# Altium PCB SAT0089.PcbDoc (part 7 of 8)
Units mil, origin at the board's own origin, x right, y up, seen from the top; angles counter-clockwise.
Board outline 4075 x 2715 mil, 6 copper layers (Top Layer, InternalPlane1, MidLayer1, Internal Plane 3, InternalPlane2, Bottom Layer), stack 67.4 mil thick; 538 components, 405 nets, 1716 pads, 1236 vias.
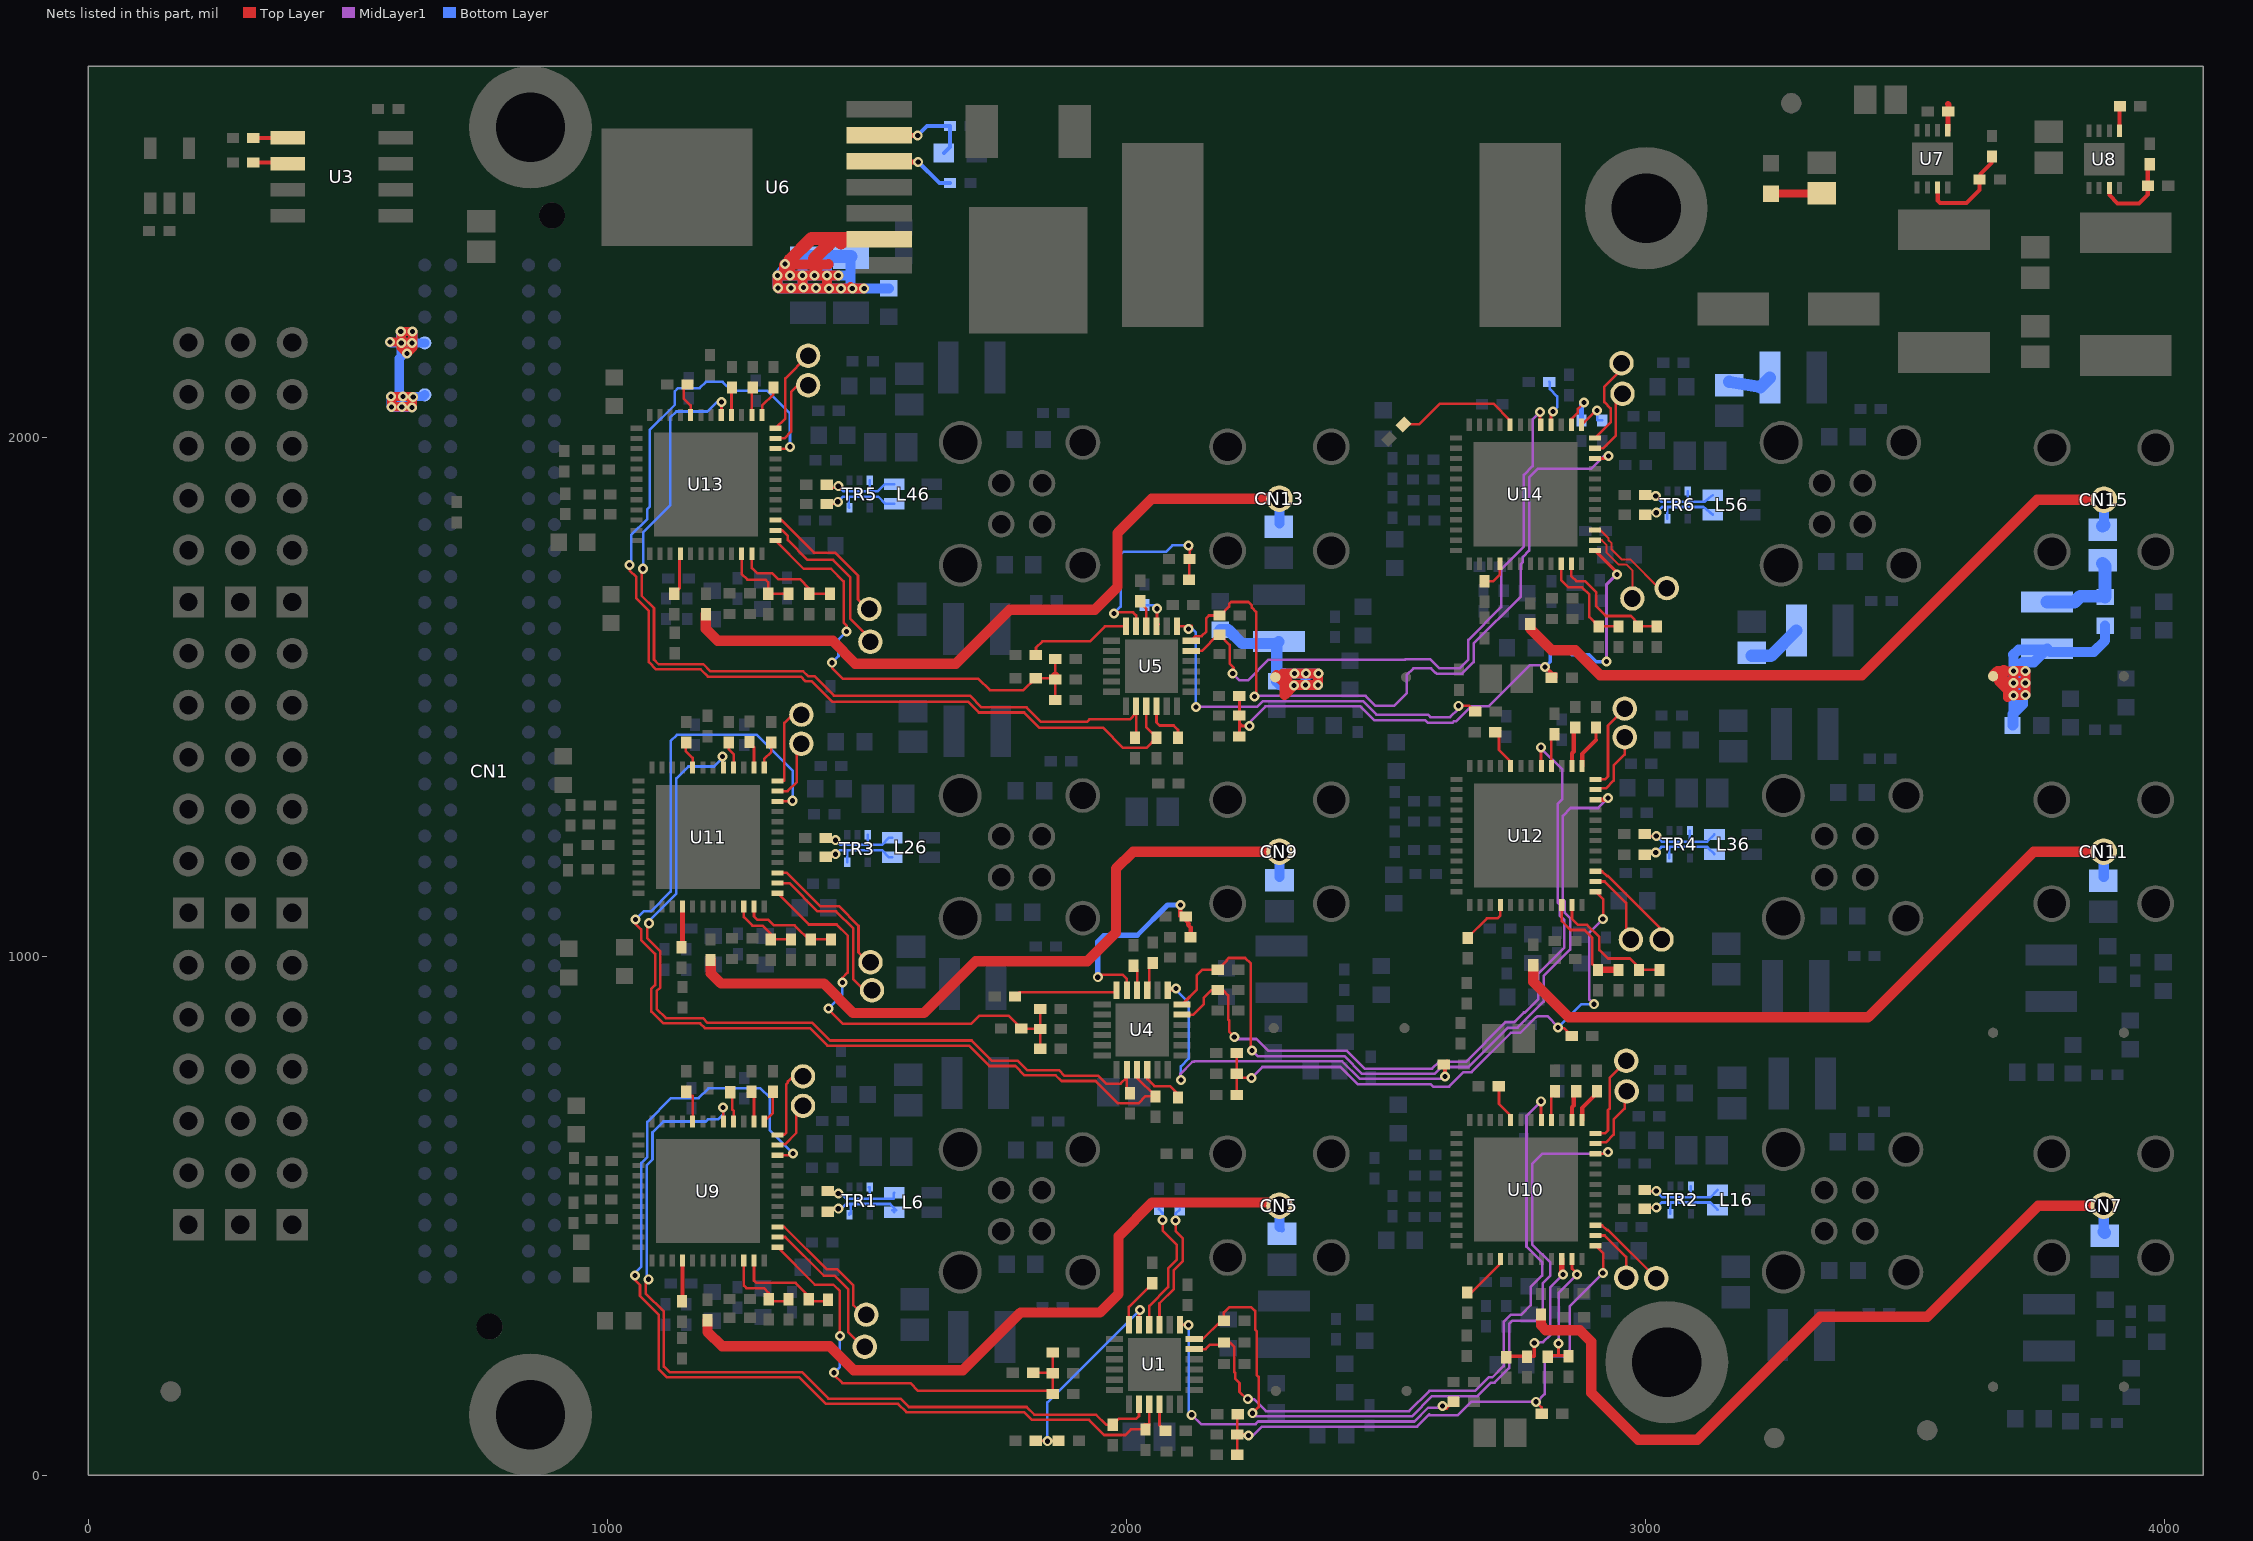
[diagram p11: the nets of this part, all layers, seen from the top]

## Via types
v1: diameter 19.29, hole 9.84, Top Layer to Bottom Layer, tented both sides, 1155 vias
v2: diameter 19.68, hole 7.87, Top Layer to Bottom Layer, tented both sides, 80 vias
v3: diameter 22, hole 10, Top Layer to Bottom Layer, tented both sides, 1 vias

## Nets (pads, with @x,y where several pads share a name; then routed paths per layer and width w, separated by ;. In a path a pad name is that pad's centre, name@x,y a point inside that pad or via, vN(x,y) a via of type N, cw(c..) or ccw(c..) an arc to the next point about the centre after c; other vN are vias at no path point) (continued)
NetL48_2: L48.2 L49.1 R125.2 R126.1 | length 719.7
  Top Layer w8: v1(2323,1522) 2315.72,1522 2314.72,1523 2292.36,1545.35 2323.65,1545.35 v1(2324,1545)
  Top Layer w19.29: L49.1@2288.98,1541.94 2305,1525.92 ; 2301.85,1545 v1(2324,1545) v1(2346,1545) v1(2370,1545) 2369,1544 v1(2369,1523) v1(2345,1523) v1@2323,1523 ; 2305,1525.92 2307.92,1523 2314.72,1523 2316.68,1523 v1@2323,1523 ; 2305,1525.92 2305,1504 v1(2323,1522) v1@2323,1523
  Top Layer w19.68: 2301.85,1545 2298.27,1541.42 v1@2316.68,1523
  Bottom Layer w19.29: R126.1@2297.5,1523 v1@2323,1523 ; R126.1@2304.5,1545 v1(2324,1545) v1(2346,1545) ; v1(2323,1522) v1@2323,1523 ; v1(2369,1523) v1(2345,1523) ; v1(2370,1545) v1(2346,1545) ; v1@2323,1523 v1(2345,1523) ; v1(2345,1523) 2345,1544 v1(2346,1545)
  Bottom Layer w22: R125.2@2181,1629.5 2196.5,1629.5 2223,1603 L48.2@2290.28,1603 ; L48.2@2294,1606.72 L48.2@2290.28,1603 ; R126.1@2297.5,1523 R126.1@2290,1530.5 ; R126.1@2304.5,1545 R126.1@2290,1530.5 ; R126.1@2290,1530.5 R126.1@2290,1530.56 2290,1602.72 L48.2@2290.28,1603
NetL54_1: L54.1 R146.1 | length 86.2
  Bottom Layer w24: R146.1@3162,2107 3163.06,2106.82 3221.56,2097 L54.1@3239.84,2115.28
NetL55_1: L55.1 R147.1 | length 106
  Bottom Layer w24: R147.1@3205,1579 3241.72,1579 L55.1@3290.72,1628
NetL58_1: L58.1 R148.1 R149.1 | length 183.6
  Bottom Layer w25: L58.1@3774,1683.28 3827.28,1683.28 3838,1694 3884.5,1694 3886,1692.5 R149.1@3886,1692.56 3886,1752 R148.1@3881,1757
NetL58_2: L58.2 L59.1 R149.2 R150.1 | length 932.7
  Top Layer w17.72: v1(3709,1503) 3702,1503 3698,1499 3698,1514 3698,1520.92 3680.89,1538.03 3674.98,1543.94 3681.05,1550 3690.89,1550 v1(3709,1550)
  Top Layer w19.29: L59.1@3671.98,1543.94 3678.05,1550 3681.05,1550 ; 3680.89,1540 3680.89,1538.03 3680.89,1531.11 3698,1514 v1(3709,1503) ; 3693.89,1527 v1(3709,1527) ; v1(3709,1503) v1(3709,1527) ; v1(3709,1503) 3710,1504 v1(3732,1504) v1(3732,1527) ; v1(3709,1527) v1(3709,1550) v1(3732,1550) v1(3732,1527) ; v1(3709,1527) v1(3732,1527)
  Top Layer w24: 3690.89,1550 3680.89,1540 3693.89,1527
  Bottom Layer w19.29: R150.1@3709,1446.5 3709,1468 v1(3709,1503) v1(3709,1527) v1(3709,1550) 3709,1581 ; v1@3727,1504 v1(3732,1504) ; v1@3727,1527 v1(3732,1527) ; v1@3727,1550 v1(3732,1550) ; L58.2@3774,1592.72 3779.72,1587 3864,1587 3886,1609 R149.2@3886,1637.44 R149.2@3886,1637.5
  Bottom Layer w20: R150.1@3709,1446.5 3707.5,1445 3707.5,1466.5 3709,1468 3727,1486 3727,1504 3727,1527 3727,1550 3727,1567 3748.28,1567 L58.2@3772.28,1591 ; 3709,1581 3719,1591 L58.2@3772.28,1591 ; L58.2@3774,1592.72 L58.2@3772.28,1591
NetLD1_2: LD1.2 R16.1 | length 93
  Top Layer w16: LD1.2@3247,2470.04 R16.1@3340,2470.47
NetR2_1: R2.1 R3.1 U1.11 | length 399.4
  Top Layer w5: R2.1@1826,67 1847,67 v1(1848,66) 1849,67 R3.1@1869,67 ; U1.11@2024.47,290.77 2024.47,317.47 v1(2026,319)
  Bottom Layer w5: v1(1848,66) 1848,141 v1(2026,319)
NetR4_1: R4.1 U1.12 | length 98
  Top Layer w5: U1.12@2004.79,290.77 2004.79,324.79 R4.1@2050,370
NetR5_2: R5.2 U3.1 | length 67
  Top Layer w8: R5.2@318.27,2576.85 318.46,2577.05 U3.1@385.21,2577.05
NetR6_1: R6.1 U3.2 | length 68
  Top Layer w8: R6.1@318.27,2529.61 382.65,2529.61 U3.2@385.21,2527.05
NetR7_1: R7.1 R8.1 U4.11 | length 419.6
  Top Layer w5: v1@1945.5,959.5 v1(1945,960) 1950,965 1993,965 2001.02,956.98 U4.11@2001.02,935.12
  Top Layer w8: v1(2104,1099) 2104,1078 2106,1076 2107,1077 R8.1@2114.68,1077 2115,1077 2115,1069 2121,1063 2119,1061 2124,1056 R7.1@2124,1037
  Bottom Layer w10: v1(1945,960) 1945,1029 1956,1040 1967,1040 1968,1041 2021,1041 2079,1099 v1(2104,1099)
NetR9_1: R9.1 U4.12 | length 200.4
  Top Layer w5: R9.1@1786,923 1794,931 1977.22,931 U4.12@1981.34,935.12
NetR10_1: R10.1 R11.1 U5.11 | length 396.4
  Top Layer w5: v1(1976,1661) 1978,1663 2013,1663 2018.74,1657.26 U5.11@2018.74,1635.91 ; v1(2120,1792) 2119,1791 2125,1785 2122,1782 2122,1765 2124,1763 2121,1760 R10.1@2121,1726
  Bottom Layer w5: v1(1976,1661) 1989,1674 1989,1774 1995,1780 2077,1780 2089,1792 v1(2120,1792)
NetR12_1: R12.1 U5.12 | length 204
  Top Layer w5: R12.1@1826,1581 1826,1595 1838,1607 1930,1607 1958.91,1635.91 U5.12@1999.06,1635.91
NetR13_2: R13.2 R14.1 U6.6 | length 183.1
  Top Layer w9.84: U6.6@1542,2583 1543,2582 v1(1598,2582)
  Bottom Layer w8: v1(1598,2582) 1616,2600 R13.2@1660.31,2600 1660.31,2559.81 R14.1@1648.5,2548
NetR15_1: R15.1 U6.5 | length 136.1
  Top Layer w9.84: U6.5@1542,2533 1544,2531 v1(1599,2531)
  Bottom Layer w8: v1(1599,2531) 1640,2490 R15.1@1660.32,2490
NetR17_1: R17.1 U7.5 | length 65.8
  Top Layer w9.84: U7.5@3582.98,2591.66 3582.98,2642.53
  Top Layer w11.81: 3582.98,2642.53 3584,2641.51 R17.1@3584,2628
NetR18_1: R18.1 U8.5 | length 50.4
  Top Layer w7.87: U8.5@3913.69,2587.72 3913.69,2637.69 R18.1@3914,2638
NetR19_1: R19.1 R20.1 U7.3 | length 198
  Top Layer w8: U7.3@3563.3,2481.43 3563.3,2456.7 3568,2452 3619,2452 3643.69,2476.69 3643.69,2497.17 3645.69,2499.17 3645.69,2507.69 3667,2529 R20.1@3667,2538.81 ; R20.1@3667,2538.81 3667,2540 3668,2541 3664.81,2541 R20.1@3667,2538.81
NetR21_1: R21.1 R22.1 U8.3 | length 157.8
  Top Layer w7.87: U8.3@3894.01,2477.49 3894.01,2466.99 3910,2451 3951,2451 3968,2468 3968,2522 R22.1@3972,2526
NetR32_2: R32.2 U9.8 | length 69.6
  Top Layer w5: R32.2@1152,739 1152,731.53 1164.47,731.53 U9.8@1164.47,681.86
NetR33_2: R33.2 U9.28 | length 78.5
  Top Layer w7.01: R33.2@1144,336 1144.79,336.79 U9.28@1144.79,414.14
NetR34_2: R34.2 R38.1 U9.35 | length 202.2
  Top Layer w5: U9.35@1282.58,414.14 1282.58,375.42 1287,371 1363,371 1388,346 1388,340 1392,336 1422,336 R38.1@1425,339
NetR35_2: R35.2 R39.1 U9.34 | length 155.3
  Top Layer w5: U9.34@1262.9,414.14 1262.9,366.1 1268,361 1302,361 1311,352 1311,340 1315,336 1345,336 R35.2@1349,340
NetR36_1: R36.1 U9.1 | length 64.1
  Top Layer w5: U9.1@1302.27,681.86 1319,698.59 R36.1@1319,739
NetR37_2: R37.2 U9.2 | length 59
  Top Layer w5: R37.2@1278,739 1282.58,734.42 U9.2@1282.58,681.86
NetR42_1: R42.1 U9.4 | length 58.7
  Top Layer w5: R42.1@1237,738 1241,734 1241,705 1243.21,702.79 U9.4@1243.21,681.86
NetR44_2: R44.2 R45.2 R48.2 R49.2 U9.37 | length 874.6
  Top Layer w5: U9.37@1327.86,439.81 1400.17,367.5 1435.5,367.5 1448,355 v1(1448,269) ; v1(1437,198) 1437,194 1453,178 1584,178 1599,163 1852,163 1858,157 R48.2@1858,197 ; R44.2@1821,198 1857,198 R48.2@1858,197 ; R45.2@1858,237 R48.2@1858,197
  Bottom Layer w5: v1(1437,198) 1448,209 v1(1448,269)
NetR58_2: R58.2 U10.8 | length 74.5
  Top Layer w5: R58.2@2718,750 2718,716 2740.47,693.53 U10.8@2740.47,684.86
NetR59_2: R59.2 R63.1 U10.35 | length 247.5
  Top Layer w5: U10.35@2858.58,417.14 2858.58,398.42 2868,389 v1(2868,387)
  Top Layer w6: R59.2@2812,229 2812,231 2833,231 ; v1(2833,254) 2833,231 ; R63.1@2852,230 2852,231 2833,231
  MidLayer1 w5: v1(2833,254) 2833,352 v1(2868,387)
NetR60_2: R60.2 R64.1 U10.34 | length 279.5
  Top Layer w6: R64.1@2732,228 2732,229.77 R60.2@2772,229.77 ; R60.2@2772,229 R60.2@2772,229.77 ; v1(2786,255) 2786,229.77 R60.2@2772,229.77
  Top Layer w9.84: v1@2838.9,389.1 U10.34@2838.9,417.14
  Top Layer w12: v1@2838.9,389.1 v1(2841,387)
  MidLayer1 w5: v1@2784,257 v1@2786,257 ; v1(2786,255) v1@2786,257 ; v1(2841,387) 2817,363 2817,271 2803,257 v1@2786,257
NetR61_1: R61.1 U10.1 | length 67.6
  Top Layer w8: U10.1@2878.27,684.86 2878.27,708.27 2906,736 2907,736 R61.1@2907,740
NetR62_2: R62.2 U10.2 | length 61.6
  Top Layer w8: U10.2@2858.58,684.86 2858.58,709.58 2862,713 2862,734 2867,734 R62.2@2867,740
NetR66_1: R66.1 U10.4 | length 62.4
  Top Layer w5: U10.4@2819.21,684.86 2819,684.86 2819,733 2826,733 R66.1@2826,740
NetR68_2: R68.2 R71.2 R72.2 R73.2 U10.37 | length 1091.3
  Top Layer w5: R71.2@2214,40 R72.2@2214,79 ; R73.2@2215,118 2215,117 2214,117 R72.2@2214,79 ; v1(2235,77) 2233,79 R72.2@2214,79 ; R68.2@2800,119 2800,131 v1(2789,142) ; U10.37@2903.86,442.81 2919,427.67 2919,395 2918,395 v1(2918,390) ; v1(2789,142) 2789,143 2790,143 v1(2789,142)
  MidLayer1 w5: v1(2235,77) 2244,77 2261,94 2560,94 2583.5,117.5 2585,116 2638.5,116 2664.5,142 v1(2789,142) 2791,142 2806,157 2806,219 2817,230 2842,230 2854,242 2854,326 v1(2918,390)
NetR82_2: R82.2 U11.8 | length 54.1
  Top Layer w5: R82.2@1152,1412 1151,1411 1151,1396 1164.47,1382.53 U11.8@1164.47,1363.86
NetR83_2: R83.2 R87.1 U11.35 | length 191.4
  Top Layer w5: U11.35@1282.58,1096.14 1282.58,1077 1288.58,1071 1310,1071 1321,1060 1361,1060 1392,1029 R83.2@1392,1032.69 1392,1033 R87.1@1431,1033
NetR84_2: R84.2 R88.1 U11.34 | length 135.1
  Top Layer w5: U11.34@1262.9,1096.14 1262.9,1076.1 1279.5,1059.5 1299,1059.5 1315,1043.5 1315,1033 R84.2@1354,1033
NetR85_1: R85.1 U11.1 | length 53.8
  Top Layer w5: U11.1@1302.27,1363.86 1302.27,1380.27 1316,1394 R85.1@1316,1412
NetR86_2: R86.2 U11.2 | length 51.7
  Top Layer w5: R86.2@1274,1412 1282.58,1403.42 U11.2@1282.58,1363.86
NetR90_1: R90.1 U11.4 | length 52
  Top Layer w5: R90.1@1234,1412 1234,1399 1243.21,1389.79 U11.4@1243.21,1363.86
NetR92_2: R92.2 R95.2 R96.2 R97.2 U11.37 | length 847.1
  Top Layer w5: U11.37@1327.86,1121.81 1388.17,1061.5 1442,1061.5 1463.25,1040.25 1463,1040 1463,969 1453,959 v1(1453,950) ; v1(1426,900) 1426,898 1454,870 1701,870 1717,886 1773,886 1798,861 1833,861 R96.2@1834,860 ; R97.2@1834,822 R96.2@1834,860 ; R95.2@1834,899 R96.2@1834,860
  Bottom Layer w5: v1(1426,900) v1@1428,900 ; v1@1431,897 v1@1428,900 ; v1(1453,950) 1453,927 1427,901 v1@1428,900
NetR106_2: R106.2 U12.8 | length 85.7
  Top Layer w5: R106.2@2711,1432 2713,1434 2717,1434 2718,1435 2718,1398 2740.47,1375.53 U12.8@2740.47,1366.86
NetR107_2: R107.2 R111.1 U12.35 | length 252.8
  Top Layer w5: U12.35@2858.58,1099.14 2858.58,1072.42 2870,1061 2888,1061 2911.5,1037.5 2911.5,1012.5 2928,996 2970,996 2987.65,978.35 2987.65,974.37 R111.1@3027.02,974.37
NetR108_2: R108.2 R112.1 U12.34 | length 209
  Top Layer w5: U12.34@2838.9,1099.14 2838.9,1068.1 2856,1051 2883,1051 2898,1036 2898,985.28 R112.1@2908.91,974.37
  Top Layer w12: R112.1@2908.91,974.37 R108.2@2948.28,974.37
NetR109_1: R109.1 U12.1 | length 85.2
  Top Layer w6: 2905,1417 R109.1@2905,1441
  Top Layer w8: U12.1@2878.27,1366.86 2878.27,1390.27 2905,1417
NetR110_2: R110.2 U12.2 | length 76.8
  Top Layer w8: U12.2@2858.58,1366.86 2858.58,1391.58 2862,1395 2862,1438 R110.2@2865,1441
NetR114_1: R114.1 U12.4 | length 63.8
  Top Layer w5: U12.4@2819.21,1366.86 2819,1366.86 2819,1422 R114.1@2825,1428
NetR116_2: R116.2 R119.2 R120.2 R121.2 U12.37 | length 1158
  Top Layer w5: R119.2@2213,733 R120.2@2213,774 ; R121.2@2213,814 R120.2@2213,774 ; v1(2241,766) 2221,766 R120.2@2213,774 ; v1(2832,863) 2833,862 2843,862 R116.2@2858,847 ; U12.37@2903.86,1124.81 2919,1109.67 2919,1077 2918,1077 v1(2918,1072)
  MidLayer1 w5: v1@2240,769 2240,765 v1(2241,766) 2262,787 2412.5,787 2445.5,754 2586,754 2591,749 2622,749 2650,777 2665,777 2741,853 2759,853 2789,883 2790,883 2792,885 2811,885 2832,864 v1(2832,863) ; v1(2901,908) 2892,917 2892,1046 v1(2918,1072)
  Bottom Layer w5: v1(2832,863) 2877,908 v1(2901,908)
NetR130_2: R130.2 U13.8 | length 83.5
  Top Layer w5: U13.8@1160.47,2043.39 1160.47,2062 1147,2075.47 R130.2@1147,2094 ; R130.2@1147,2094 1147,2102 R130.2@1154.69,2102 1155,2102 R130.2@1147,2094
NetR131_2: R131.2 R135.1 U13.35 | length 204
  Top Layer w5: U13.35@1278.58,1775.67 1278.58,1748.42 1289,1738 1318,1738 1329,1727 1371,1727 1389,1709 1389,1699 R135.1@1429,1699
NetR132_2: R132.2 R136.1 U13.34 | length 157.3
  Top Layer w5: U13.34@1258.9,1775.67 1258.9,1737.1 1270,1726 1305,1726 1310,1721 1310,1699 R132.2@1349,1699
NetR133_1: R133.1 U13.1 | length 61.6
  Top Layer w5: U13.1@1298.27,2043.39 1298.27,2061.27 1320,2083 R133.1@1320,2096
NetR134_2: R134.2 U13.2 | length 53.2
  Top Layer w5: U13.2@1278.58,2043.39 1278.58,2094.58 R134.2@1280,2096
NetR138_1: R138.1 U13.4 | length 52.9
  Top Layer w5: U13.4@1239.21,2043.39 1239.21,2095.21 R138.1@1240,2096
NetR140_2: R140.2 R143.2 R144.2 R145.2 U13.37 | length 899.9
  Top Layer w5: U13.37@1323.86,1801.26 1378.2,1747 1431,1747 1455.5,1722.5 1455.5,1643 1461,1637.5 v1(1461,1626) ; v1(1433,1566) 1433,1556 1454,1535 1715,1535 1737,1513 1801.66,1513 1824.66,1536 R140.2@1825.69,1536 1860.46,1536 1862.91,1536 R144.2@1868,1536 ; R145.2@1862.91,1494.17 R144.2@1862.91,1533.54 ; R143.2@1862.91,1572.91 1862.91,1541.09 R144.2@1868,1536 ; R144.2@1870.46,1533.54 R144.2@1868,1536
  Top Layer w15.75: R144.2@1860.46,1536 1862.91,1533.54 1862.91,1536 R144.2@1862.91,1541.09
  Bottom Layer w5: v1(1433,1566) 1445.5,1578.5 1445.5,1610.5 v1(1461,1626)
NetR154_2: R154.2 U14.8 | length 244
  Top Layer w5: R154.2@2534.14,2025.14 2564.14,2025.14 2604,2065 2707,2065 2739.47,2032.53 U14.8@2739.47,2023.86
NetR155_2: R155.2 R159.1 U14.35 | length 247.9
  Top Layer w5: U14.35@2857.58,1756.67 2857.58,1732.42 2867,1723 2884,1723 2905,1702 2905,1675 2924,1656 2972,1656 2986,1642 2986,1636 R159.1@3022,1636
NetR156_2: R156.2 R160.1 U14.34 | length 203.8
  Top Layer w5: U14.34@2837.9,1756.67 2837.9,1725.1 2852,1711 2878,1711 2892,1697 2892,1654 2910,1636 R156.2@2948,1636
NetR157_1: R157.1 U14.1 | length 70.2
  Top Layer w5: U14.1@2877.27,2024.39 2904.88,2052 v1(2907,2052)
  Bottom Layer w5: v1(2907,2052) 2907,2033 R157.1@2917,2033
NetR158_2: R158.2 U14.2 | length 88.8
  Top Layer w5: U14.2@2857.58,2024.39 2857.58,2035.58 2870,2048 2870,2055 v1(2882,2067)
  Bottom Layer w10: R158.2@2877,2033 2877,2062 v1(2882,2067)
NetR162_1: R162.1 U14.4 | length 96.5
  Top Layer w5: U14.4@2818.21,2024.39 2818.21,2046.21 v1(2822,2050) v1@2824,2048
  Bottom Layer w5: R162.1@2815,2107 2816,2106 2816,2093 2830,2079 2830,2058 v1(2822,2050)
NetR164_2: R164.2 R167.2 R168.2 R169.2 U14.37 | length 1189.5
  Top Layer w5: R167.2@2218,1424 2218,1443 ; R169.2@2218,1502 2218,1450 ; v1(2237,1444) 2224,1444 ; 2218,1443 2218,1450 ; 2218,1443 2219,1444 2224,1444 ; 2218,1450 2224,1444
  Top Layer w6.5: U14.37@2902.86,1782.26 2945,1740.2 v1(2945,1736)
  Top Layer w8: v1(2807,1558) 2821,1544 2827,1544 2827,1537 R164.2@2819.31,1537 R164.2@2819,1537
  MidLayer1 w5: v1(2237,1444) 2237,1451 2268,1482 2451,1482 2478,1455 2576,1455 2580.5,1450.5 2628.5,1450.5 2631,1453 2635,1453 2664,1482 2698,1482 2777,1561 2804,1561 v1(2807,1558)
  MidLayer1 w6.5: v1(2925,1568) 2925,1716 v1(2945,1736)
  Bottom Layer w6.5: v1(2807,1558) v1@2809,1560 ; v1@2809,1562 v1@2809,1560 ; v1(2925,1568) 2905,1568 2892,1581 2858,1581 2847,1592 2826,1592 2817,1583 2817,1568 v1@2809,1560
NetR171_2: R171.2 U10.28 | length 99.5
  Top Layer w5: R171.2@2657,353 R171.2@2657,352.69 2657,350 2662,350 2720.79,408.79 U10.28@2720.79,417.14
NetR174_2: R174.2 U11.28 | length 78.9
  Top Layer w9.84: R174.2@1144.79,1020.14 U11.28@1144.79,1096.14
  Top Layer w10: R174.2@1142.76,1018.11 R174.2@1144.79,1020.14
NetR177_2: R177.2 U12.28 | length 101.5
  Top Layer w5: R177.2@2658,1036 2658,1037 2694.5,1073.5 2715.5,1073.5 2720.79,1078.79 U12.28@2720.79,1099.14
NetR180_2: R180.2 U13.28 | length 81.3
  Top Layer w5: R180.2@1128.98,1699.21 1139,1709.24 1139,1773.88 U13.28@1140.79,1775.67
NetR183_2: R183.2 U14.28 | length 56
  Top Layer w5: R183.2@2690,1723 2707,1723 2719.79,1735.79 U14.28@2719.79,1756.67
NetR185_1: R185.1 U1.9 | length 249.5
  Top Layer w5: U1.9@2063.84,290.77 2063.84,331.84 2091.5,359.5 2091.5,395.5 2109,413 2109,457 2095,471 v1(2095,491)
  Bottom Layer w5: v1(2095,491) 2095,504.5 R185.1@2103,512.5
NetR186_1: R186.1 U1.10 | length 258.6
  Top Layer w5: U1.10@2044.16,290.77 2044.16,326.66 2080.5,363 2080.5,399 2097.5,416 2097.5,444.5 2070,472 v1(2070,492)
  Bottom Layer w5: R186.1@2063,513 2070,506 v1(2070,492)
NetR187_1: R187.1 U4.10 | length 48.7
  Top Layer w5: R187.1@2014,981 2020.71,974.29 U4.10@2020.71,935.12
NetR188_1: R188.1 U4.9 | length 56.3
  Top Layer w5: U4.9@2040.39,935.12 2044,938.72 2044,980 R188.1@2051,987
NetR189_1: R189.1 U5.9 | length 64.4
  Top Layer w5: U5.9@2058.11,1635.91 2062,1639.8 2059,1642.8 v1(2059,1670)
  Bottom Layer w5: R189.1@2035,1677 2053,1677 2059,1671 v1(2059,1670)
NetR190_1: R190.1 U5.10 | length 52.8
  Top Layer w5: R190.1@2027,1684 2027,1681 2038,1670 2038,1661 2038.43,1660.57 U5.10@2038.43,1635.91
NetTP1_1: TP1.1 U9.38 | length 307.2
  Top Layer w5: U9.38@1327.86,459.42 1342.58,459.42 1417,385 1438,385 1464,359 1464,276 1494,246 1496,246 TP1.1@1496,248
NetTP2_1: TP2.1 U9.39 | length 266.3
  Top Layer w5: U9.39@1327.86,479.1 1340.9,479.1 1422.5,397.5 1442.5,397.5 1474,366 1474,328 1494,308 1499,308 TP2.1@1499,310
NetTP3_1: TP3.1 U9.48 | length 170.2
  Top Layer w5: U9.48@1327.86,656.27 1340,656.27 1345,661.27 1345,754 1348,757 1348,759 1373,784 1377,780 TP3.1@1377,769
NetTP4_1: TP4.1 U9.47 | length 115.1
  Top Layer w5: U9.47@1327.86,636.58 1329.28,638 1342,638 1364,660 1364,715 1367,712 TP4.1@1377,712
NetTP5_1: TP5.1 U10.38 | length 116.3
  Top Layer w5: U10.38@2903.86,462.42 2921.58,462.42 2963,421 TP5.1@2963,381
NetTP6_1: TP6.1 U10.39 | length 159.4
  Top Layer w5: U10.39@2903.86,482.1 2916.9,482.1 2926,473 2928,473 TP6.1@3021,380
NetTP7_1: TP7.1 U10.48 | length 175
  Top Layer w5: U10.48@2903.86,659.27 2922.27,659.27 2928,665 2928,704 2931,707 2931,766 2963,798 TP7.1@2963,799
NetTP8_1: TP8.1 U10.47 | length 135.7
  Top Layer w5: U10.47@2903.86,639.58 2906.28,642 2924,642 2939,657 2939,686 2960,707 2960,736 TP8.1@2964,740
NetTP9_1: TP9.1 U11.38 | length 325
  Top Layer w5: U11.38@1327.86,1141.42 1350.58,1141.42 1405,1087 1441,1087 1474,1054 1474,956 1495,935 TP9.1@1510,935
NetTP10_1: TP10.1 U11.39 | length 280.3
  Top Layer w5: U11.39@1327.86,1161.1 1345.9,1161.1 1410,1097 1446,1097 1484,1059 1484,1008 1503,989 TP10.1@1507,989
NetTP11_1: TP11.1 U11.48 | length 169.5
  Top Layer w5: U11.48@1327.86,1338.27 1341,1338.27 1341,1450 1363,1472 1369,1466 TP11.1@1374,1466
NetTP12_1: TP12.1 U11.47 | length 122.1
  Top Layer w5: U11.47@1327.86,1318.58 1347.58,1318.58 1365,1336 1365,1399 1374,1408 TP12.1@1374,1410
NetTP13_1: TP13.1 U12.38 | length 150.5
  Top Layer w5: U12.38@2903.86,1144.42 2921.58,1144.42 2963,1103 2963,1041.73 TP13.1@2972.13,1032.61
NetTP14_1: TP14.1 U12.39 | length 193
  Top Layer w5: U12.39@2903.86,1164.1 2916.9,1164.1 2926,1155 2928,1155 3031.18,1051.82 TP14.1@3031.18,1032.61
NetTP15_1: TP15.1 U12.48 | length 178.8
  Top Layer w5: U12.48@2903.86,1341.27 2922.27,1341.27 2928,1347 2928,1445 2963,1480 TP15.1@2963,1480.17 ; TP15.1@2960.32,1477.49 TP15.1@2963,1480.17 ; TP15.1@2963,1481 TP15.1@2963,1480.17
NetTP16_1: TP16.1 U12.47 | length 139.5
  Top Layer w5: U12.47@2903.86,1321.58 2906.28,1324 2924,1324 2939,1339 2939,1368 2960,1389 2960,1418 2964,1422 2963.63,1422.37 TP16.1@2960.32,1422.37
NetTP17_1: TP17.1 U13.38 | length 326.8
  Top Layer w5: U13.38@1323.86,1820.94 1337.06,1820.94 1348,1810 1348,1802 1386,1764 1435,1764 1468,1731 1468,1651 1506.93,1612.07 TP17.1@1506.93,1606.38
NetTP18_1: TP18.1 U13.39 | length 279
  Top Layer w5: U13.39@1323.86,1840.63 1335.37,1840.63 1398,1778 1439,1778 1483,1734 1483,1688 1501.63,1669.37 TP18.1@1504.96,1669.37
NetTP19_1: TP19.1 U13.48 | length 165.9
  Top Layer w5: U13.48@1323.86,2017.8 1343,2036.94 1343,2113.71 TP19.1@1386.85,2157.56
NetTP20_1: TP20.1 U13.47 | length 150.5
  Top Layer w5: U13.47@1323.86,1998.11 1341.11,1998.11 1354,2011 1354,2088 1366.47,2100.47 TP20.1@1386.85,2100.47
NetTP21_1: TP21.1 U14.38 | length 158.6
  Top Layer w4.02: U14.38@2902.86,1801.94 2916.06,1801.94 2925,1793 2925,1779 2949,1755 2964,1755 2975.06,1743.94 TP21.1@2975.06,1689.74
NetTP22_1: TP22.1 U14.39 | length 193.9
  Top Layer w4.02: U14.39@2902.86,1821.63 2913.37,1821.63 2929,1806 2929,1802 2935,1796 2935,1784 2954,1765 2971,1765 3026.23,1709.77 TP22.1@3041.02,1709.77
NetTP23_1: TP23.1 U14.48 | length 175.3
  Top Layer w5: U14.48@2902.86,1998.8 2933,2028.94 2933,2056 2921,2068 2921,2098 2954,2131 TP23.1@2954,2143
NetTP24_1: TP24.1 U14.47 | length 135.8
  Top Layer w5: U14.47@2902.86,1979.11 2918.11,1979.11 2943,2004 2943,2071 TP24.1@2956,2084
OEN_CAM1: R43.1 U1.20 U9.5 | length 1660.7
  Top Layer w5: v1(1079,378) 1074,373 1074,351 1109,316 1109,210 1120,199 1375,199 1426,148 1565,148 1581,132 1808,132 1823,117 1942,117 1961,98 R43.1@1974,98 ; v1(1223,709) 1223,682.39 U9.5@1223.53,681.86 ; R43.1@1974,93 R43.1@1974,97.68 R43.1@1974,98 ; U1.20@2024.47,137.23 2024.47,114.47 2019,109 1985,109 R43.1@1974,98
  Bottom Layer w5: v1(1079,378) 1076,381 1076,598 1087,609 1087,661 1108,682 1190,682 1194,686 1213,686 1223,696 v1(1223,709)
OEN_CAM2: R67.1 U1.5 U10.5 | length 1350
  Top Layer w5: U1.5@2130.77,243.53 2152.53,243.53 2161,252 2184,252 2188,256 R67.1@2188.32,256 2200,256 2208,248 2208,199 2210,197 2210,186 2218,178 2218,161 2232,147 v1(2234,147) ; v1(2799,721) 2799,685.39 U10.5@2799.53,684.86
  MidLayer1 w5: v1(2234,147) 2246,147 2269,124 2545,124 2584,163 2672,163 2698,189 2705,189 2727,211 2727,296 2741,310 2761,310 2779,328 2779,363 2801,385 2801,411 2771,441 2771,693 v1(2799,721)
OEN_CAM3: R91.1 U4.20 U11.5 | length 1631.6
  Top Layer w5: v1(1080,1064) 1077,1061 1077,1035 1102,1010 1102,940 1095,933 1095,899 1113,881 1184,881 1193,872 1395,872 1429,838 1702,838 1741,799 1791,799 1809,781 1870,781 1881,770 1946,770 1961,755 1989,755 U4.20@2001.02,767.02 ; v1(1222,1385) 1222,1365.39 U11.5@1223.53,1363.86 ; U4.20@2001.02,781.57 U4.20@2001.02,767.02 ; R91.1@2007,737 2007,746.46 2001.02,746.46 U4.20@2001.02,767.02
  Bottom Layer w5: v1(1080,1064) 1080,1068 1133,1121 1133,1343 1156,1366 1206,1366 1222,1382 v1(1222,1385)
OEN_CAM4: R115.1 U4.5 U12.5 | length 1439.4
  Top Layer w5: U4.5@2107.32,887.87 2129,887.87 2149,907.87 2149,920 2164.12,935.12 R115.1@2176.22,935.12 2185.88,935.12 2196,925 2196,879 2198,877 2198,855 v1(2208,845) ; v1(2799,1403) 2799,1367.39 U12.5@2799.53,1366.86
  MidLayer1 w5: v1(2208,845) 2212,841 2250.5,841 2273.5,818 2425,818 2459,784 2589,784 2602,797 2654,797 2730,873 2747,873 2766,892 2768,892 2794,918 2794,967 2844,1017 2844,1070 2835,1079 2835,1100 2831,1104 2831,1294 2840,1303 2840,1360 2799,1401 v1(2799,1403)
OEN_CAM5: R139.1 U5.20 U13.5 | length 1681.9
  Top Layer w5: v1(1069,1747) 1066,1744 1066,1695 1090,1671 1090,1572 1099,1563 1185,1563 1198.5,1549.5 1377.5,1549.5 1387,1540 1399,1540 1436.5,1502.5 1698.5,1502.5 1721,1480 1808,1480 1836,1452 1924,1452 1929,1457 2007,1457 U5.20@2018.74,1468.74 ; U13.5@1219.53,2043.39 1220,2043.86 v1(1220,2068) ; R139.1@2016.77,1421.65 2018.74,1423.62 U5.20@2018.74,1468.74 ; U5.20@2018.74,1482.36 U5.20@2018.74,1468.74
  Bottom Layer w5: v1(1069,1747) 1069,1817 1121,1869 1121,2038 1133,2050 1193,2050 1211,2068 v1(1220,2068)
OEN_CAM6: R163.1 U5.5 U14.5 | length 1206.7
  Top Layer w5: U5.5@2125.04,1588.66 2145.66,1588.66 2177,1620 R163.1@2179.32,1620 2199,1600.32 2199,1564 2207,1556 2205,1554 v1(2205,1545) ; v1(2797,2049) 2797,2027.39 2799,2025.39 2798,2024.39 2798.26,2024.12 2798.53,2023.86 U14.5@2798.53,2024.39
  MidLayer1 w5: v1(2205,1545) 2218,1532 2234,1532 2274,1572 2537,1572 2538,1573 2585,1573 2603,1555 2642,1555 2659,1572 2659,1610 2722,1673 2722,1746 2766,1790 2766,1928 2783,1945 2783,2035 v1(2797,2049)
PDB_CAM1: R40.1 U1.22 | length 55.8
  Top Layer w5: U1.22@2063.84,137.23 2063.84,97.16 R40.1@2075,86
PDB_CAM2: R170.1 U1.7 | length 730.7
  Top Layer w5: U1.7@2103.21,290.77 v1@2120,290.77 ; v1(2120,290) v1@2120,290.77 ; v1@2124.23,290.77 v1@2120,290.77 ; v1(2609,134) 2614,129 2617,129 R170.1@2630,142
  MidLayer1 w5: v1(2126,117) 2144,99 2249,99 2254,104 2555,104 2581.5,130.5 2605.5,130.5 v1(2609,134)
  Bottom Layer w5: v1(2120,290) 2120,123 v1(2126,117)
PDB_CAM3: R173.1 U4.22 | length 94.9
  Top Layer w5: U4.22@2040.39,781.57 2040.39,763.61 2054,750 2084,750 2099.45,734.55 R173.1@2099.45,728.74
PDB_CAM4: R176.1 U4.7 | length 793.4
  Top Layer w6: U4.7@2079.76,935.12 2093.12,935.12 v1(2096,938)
  Top Layer w8: v1(2614,769) 2614,789 2611,792 2612,793 2614,793 R176.1@2618,797
  MidLayer1 w5: v1(2105,762) 2104,761 2104,774 2127,797 2130,797 2131,798 2416,798 2450,764 2609,764 v1(2614,769)
  Bottom Layer w5: v1(2096,938) 2096,935 2120,911 2120,803 2105,788 v1(2105,762)
PDB_CAM5: R179.1 U5.22 | length 93.7
  Top Layer w5: U5.22@2058.11,1482.36 2058.11,1451.11 2058,1451 2064,1445 2091,1445 2099.45,1436.55 R179.1@2099.45,1421.65
PDB_CAM6: R182.1 U5.7 | length 787.4
  Top Layer w5: U5.7@2097.48,1635.91 v1@2120,1635.91 ; v1(2120,1631) v1@2120,1635.91 ; v1(2640,1483) 2661,1483 2672,1472 R182.1@2671,1471 ; R182.1@2664,1471 R182.1@2671,1471 ; R182.1@2668,1468 R182.1@2671,1471 ; v1@2120,1635.91 2120,1637 2126,1637 2124,1635 2123.09,1635.91 v1@2120,1635.91
  MidLayer1 w5: v1(2134,1481) 2252,1481 2263,1492 2456,1492 2482,1466 2581,1466 2586,1461 2624,1461 2640,1477 v1(2640,1483)
  Bottom Layer w5: v1(2120,1631) 2120,1630 2128,1630 2134,1624 v1(2134,1481)
RX1_CH0_N: C24.2 L6.2 TR1.3 | length 176.3
  Top Layer w5: C24.2@1425,548 1430,543 v1(1445,543) 1445,548 v1@1446,548
  Bottom Layer w5: v1(1445,543) 1451,543 1461,533 1506,533 ; TR1.3@1504,555.26 TR1.3@1505.37,555.26 ; TR1.3@1505.68,555.57 TR1.3@1505.37,555.26 ; L6.2@1552.98,544.98 1551.98,543.98 1551.98,533 1506,533 ; TR1.3@1505.37,555.26 1506,555.26 1506,533
RX1_CH0_P: C23.2 L6.3 TR1.5 | length 178.8
  Top Layer w5: C23.2@1425,508 1431,514 v1(1445,514)
  Bottom Layer w5: v1(1445,514) 1451,514 1460,523 1469,523 ; TR1.5@1466.31,502.43 1466.32,504.74 1469,504.74 1469,523 ; L6.3@1549.02,510.98 L6.3@1552.02,510.98 ; L6.3@1553.02,507.06 1552.02,508.06 L6.3@1552.02,510.98 ; 1469,523 1545,523 1557.02,510.98 L6.3@1552.02,510.98
RX1_CH1_P: C25.2 CN5.1 R25.2 | length 1404
  Top Layer w7.87: CN5.1@2289,526 CN5.1@2295,520
  Top Layer w20: C25.2@1193,299 1193,277 1221,249 1429,249 1475,203 1685,203 1796,314 1949,314 1985,350 1985,461 2050,526 CN5.1@2289,526
  Bottom Layer w12: R25.2@2295,479 R25.2@2300,474
  Bottom Layer w20: R25.2@2295,479 CN5.1@2295,520
RX2_CH0_N: C56.2 L16.2 TR2.3 | length 173.7
  Top Layer w5: C56.2@2999,550 3001,548 v1(3021,548)
  Bottom Layer w5: v1(3021,548) 3033,536 3089,536 ; TR2.3@3087.68,557.57 3087.68,537.32 3089,536 ; L16.2@3138.98,549.98 3125,536 3089,536
RX2_CH0_P: C55.2 L16.3 TR2.5 | length 172.5
  Top Layer w5: C55.2@2999,514 3001,516 v1(3021,516)
  Bottom Layer w5: v1(3021,516) 3031,526 3048,526 ; TR2.5@3048.31,504.43 3048,504.74 3048,526 ; L16.3@3139.02,512.06 3125.08,526 3048,526
RX2_CH1_P: C57.2 CN7.1 R52.2 | length 1493.8
  Top Layer w20: C57.2@2799,310 2799,289 2808,280 2874,280 2896,258 2896,159 2986,69 3100,69 3337,306 3543,306 3757,520 CN7.1@3883,520
  Bottom Layer w20: R52.2@3883,470 CN7.1@3883,520
  Bottom Layer w24: R52.2@3883,470 R52.2@3885,468
RX3_CH0_N: C88.2 L26.2 TR3.3 | length 159.3
  Top Layer w5: C88.2@1421,1228 1436,1228 v1(1440,1224)
  Bottom Layer w5: v1(1440,1224) 1449,1215 1503,1215 ; TR3.3@1501.68,1234.57 1501.68,1216.32 1503,1215 ; L26.2@1548.98,1228.98 1542.98,1228.98 1529,1215 1503,1215
RX3_CH0_P: C87.2 L26.3 TR3.5 | length 162.9
  Top Layer w5: C87.2@1421,1192 1435,1192 v1(1440,1197)
  Bottom Layer w5: v1(1440,1197) 1448,1205 1462,1205 ; TR3.5@1462.31,1181.43 1462,1181.74 1462,1205 ; L26.3@1549.02,1191.06 1542.94,1191.06 1529,1205 1462,1205
RX3_CH1_P: C89.2 CN9.1 R76.2 | length 1402.8
  Top Layer w20: C89.2@1199,993 1199,968 1219,948 1417,948 1474,891 1610,891 1710,991 1925,991 1980,1046 1980,1169 2013,1202 CN9.1@2295,1202
  Bottom Layer w20: R76.2@2295,1153 CN9.1@2295,1202
RX4_CH0_N: C120.2 L36.2 TR4.3 | length 167.7
  Top Layer w5: C120.2@2999,1236 3003,1232 v1(3021,1232)
  Bottom Layer w5: v1(3021,1232) 3032,1221 3086,1221 ; TR4.3@3085.68,1242.57 3085.68,1221.32 3086,1221 ; L36.2@3132.98,1234.98 3119,1221 3086,1221
RX4_CH0_P: C119.2 L36.3 TR4.5 | length 168.3
  Top Layer w5: C119.2@2999,1196 3003,1200 v1(3020,1200)
  Bottom Layer w5: v1(3020,1200) 3031,1211 3048,1211 ; TR4.5@3046.31,1189.43 3046.32,1209.32 3048,1211 ; L36.3@3133.02,1197.06 3121.08,1209 3121,1209 3119,1211 3048,1211
RX4_CH1_P: C121.2 CN11.1 R101.2 | length 1341.7
  Top Layer w20: C121.2@2784,983 2784,951 2852,883 3429,883 3748,1202 CN11.1@3883,1202
  Bottom Layer w15.75: R101.2@3882,1152 R101.2@3883,1153
  Bottom Layer w20: R101.2@3883,1153 CN11.1@3883,1202
RX5_CH0_N: C152.2 L46.2 TR5.3 | length 165.3
  Top Layer w5: C152.2@1423,1909 1428,1909 1434,1903 1442,1903 v1(1445,1906)
  Bottom Layer w5: v1(1445,1906) 1455,1896 1506,1896 ; TR5.3@1505.68,1917.57 1505.68,1896.32 1506,1896 ; L46.2@1552.98,1909.98 1534.98,1909.98 1521,1896 1506,1896
RX5_CH0_P: C151.2 L46.3 TR5.5 | length 164.1
  Top Layer w5: C151.2@1423,1872 1440,1872 v1(1444,1876)
  Bottom Layer w5: v1(1444,1876) 1454,1886 1465,1886 ; TR5.5@1466.31,1864.43 1465.63,1865.11 1465,1865.11 1465,1886 ; L46.3@1553.02,1872.06 1535.94,1872.06 1522,1886 1465,1886
RX5_CH1_P: C153.2 CN13.1 R124.2 | length 1402
  Top Layer w20: C153.2@1190,1659.21 1190,1631 1213,1608 1434,1608 1478,1564 1671,1564 1775,1668 1939,1668 1983,1712 1983,1816 2048.97,1881.97 CN13.1@2295,1881.97
  Bottom Layer w11.81: R124.2@2294,1834 R124.2@2295,1835
  Bottom Layer w20: R124.2@2295,1835 CN13.1@2295,1881.97
RX6_CH0_N: C184.2 L56.2 TR6.3 | length 160.8
  Top Layer w5: C184.2@3000,1889 3002,1887 v1(3020,1887)
  Bottom Layer w5: v1(3020,1887) 3031,1876 3081,1876 ; TR6.3@3081.68,1896.57 3081.68,1876.68 3081,1876 ; L56.2@3129.98,1888.98 3114,1876 3081,1876
RX6_CH0_P: C183.2 L56.3 TR6.5 | length 164.3
  Top Layer w5: C183.2@3000,1851 3004,1855 v1(3021,1855)
  Bottom Layer w5: v1(3021,1855) 3032,1866 3042,1866 ; TR6.5@3042.31,1843.43 3042.32,1865.68 3042,1866 ; L56.3@3130.02,1851.06 3112.08,1866 3042,1866
RX6_CH1_P: C185.2 CN15.1 R148.2 | length 1343
  Top Layer w8: C185.2@2778.21,1631.79 C185.2@2778.21,1640.21
  Top Layer w20: C185.2@2778.21,1631.79 2820,1590 2865,1590 2913,1542 3417,1542 3755,1880 CN15.1@3883.54,1880
  Bottom Layer w20: R148.2@3883.54,1831.54 CN15.1@3883.54,1880
  Bottom Layer w25: R148.2@3881,1829 R148.2@3883.54,1831.54
SEL_CAM1: R46.2 U1.21 U9.46 | length 1997.8
  Top Layer w5: v1(1053,385) 1053,377 1063,367 1063,346 1099,310 1099,205 1115,189 1370,189 1421,138 1560,138 1576,122 1803,122 1818,107 1928,107 1957,78 1998,78 2009,89 R46.2@2037,89 ; U9.46@1327.86,616.9 1354.9,616.9 v1(1358,620) ; R46.2@2036,98.84 R46.2@2037,98.84 ; U1.21@2044.16,137.23 R46.2@2044.16,98.84 ; R46.2@2037,89 2044.16,96.16 R46.2@2044.16,98.84 ; R46.2@2037,89 R46.2@2037,98.84 ; R46.2@2037,98.84 R46.2@2044.16,98.84
  Bottom Layer w5: v1(1053,385) 1053,390 1065.5,402.5 1065.5,602.5 1077,614 1077,681 1123,727 1176,727 1195,746 1295,746 1313,728 1313,665 v1(1358,620)
SEL_CAM2: R70.2 U1.6 U10.46 | length 1552.9
  Top Layer w5: U1.6@2130.77,263.21 2147.21,263.21 2182,298 2188,298 R70.2@2188,299 ; R70.2@2189,299 R70.2@2188,299 ; v1(2243,120) 2255,132 2255,190 2251,194 2251,278 2248,281 2248,317 2241,324 2198,324 2188,314 R70.2@2188,299 ; U10.46@2903.86,619.9 2924.9,619.9 v1(2928,623)
  MidLayer1 w5: v1(2243,120) 2249,114 2550,114 2589,153 2677,153 2703,179 2709.5,179 2737.5,207 2737.5,292 2743.25,297.75 2788.75,297.75 2802,311 2802,370 2817,385 2817,410 2782,445 2782,600 2802,620 v1@2925,620 ; v1@2925,620 v1(2928,623) 2930,621 2930,620 v1@2925,620
SEL_CAM3: R94.2 U4.21 U11.46 | length 2047.7
  Top Layer w5: v1(1054,1071) 1054,1063 1065,1052 1065,1032 1092,1005 1092,945 1085,938 1085,894 1108,871 1179,871 1188.25,861.75 1390.25,861.75 1424,828 1697,828 1736,789 1786,789 1804,771 1864,771 1875,760 1941,760 1984,717 2023,717 2037,731 R94.2@2055.85,731 ; U11.46@1327.86,1298.9 1355.9,1298.9 v1(1357,1300) ; U4.21@2020.71,781.57 2020.71,766.14 R94.2@2055.85,731 ; R94.2@2056.14,730.71 R94.2@2055.85,731
  Bottom Layer w5: v1(1054,1071) 1070,1087 1084,1087 1122,1125 1122,1415 1134,1427 1288,1427 1357,1358 v1(1357,1300)
SEL_CAM4: R118.2 U4.6 U12.46 | length 1529.6
  Top Layer w5: U4.6@2107.32,907.56 2136,936.24 2136,964 2146.49,974.49 2175.91,974.49 2193.5,992.08 2193.5,993.5 2197,997 2229,997 2240,986 2240,821 v1(2242,819)
  Top Layer w6: U4.6@2107.32,907.56 2122,922.24
  Top Layer w8: U12.46@2903.86,1301.9 2924.9,1301.9 v1(2928,1305)
  MidLayer1 w5: v1(2242,819) 2253,808 2420.5,808 2454.5,774 2594,774 2607,787 2659,787 2735,863 2754,863 2804,913 2804,962 2855,1013 2855,1074 2845,1084 2845,1106 2841,1110 2841,1271 2856,1286 2909,1286 v1(2928,1305)
SEL_CAM5: R142.2 U5.21 U13.46 | length 2055.6
  Top Layer w5: v1@1041,1759 1041,1752 v1(1043,1754) 1043,1744 1056,1731 1056,1690 1080,1666 1080,1567 1094,1553 1180,1553 1194,1539 1373,1539 1381,1531 1381,1530 1394,1530 1433,1491 1695,1491 1716,1470 1803,1470 1832,1441 1955,1441 1994,1402 2038.46,1402 2058.11,1421.65 2038.43,1441.34 U5.21@2038.43,1482.36 ; U13.46@1323.86,1978.43 1348.43,1978.43 v1(1352,1982)
  Bottom Layer w5: v1(1043,1754) 1046,1757 1046,1812 1077,1843 1077,1862 1082,1867 1082,2015 1130,2063 1130,2089 1136,2095 1178,2095 1190,2107 1222,2107 1239,2090 1308,2090 1352,2046 v1(1352,1982)
SEL_CAM6: R166.2 U5.6 U14.46 | length 1443.5
  Top Layer w5: U5.6@2125.04,1608.35 2133.69,1617 2145,1617 2154,1626 2154,1652 2159,1657 R166.2@2179.31,1657 2181,1657 2198,1674 2198,1679 2202,1683 2235,1683 2242,1676 2242,1672 2250,1664 2250,1504 v1(2247,1501) ; U14.46@2902.86,1959.43 2927.57,1959.43 2929,1960.85 v1(2929,1964)
  MidLayer1 w5: v1@2248,1501 v1(2247,1501) 2248,1502 2461,1502 2480,1483 2516,1483 2540,1507 2540,1542 2553,1555 2587,1555 2595,1547 2596,1547 2598,1545 2647,1545 2669,1567 2669,1603 2760,1694 2760,1756 2764,1760 2764,1770 2776,1782 2776,1923 2793,1940 2896,1940 2920,1964 v1(2929,1964)
VDD_12V: C7.1 C8.1 C9.1 CN1.35 CN1.37 U6.2 | length 2430.2
  Top Layer w5: v1(1342,2334.5) 1343,2333.5 1352,2324.5 1359,2317.5 1399,2317.5 1405.5,2317.5 1421.5,2333.5 1422,2334 1426,2334
  Top Layer w17.72: v1(581,2184) v1@603,2184 ; v1(624,2182) 622,2184 v1@603,2184 ; v1@603,2184 603,2203 v1(602,2204) v1(625,2204) 625,2173 v1(614,2162) 603,2173 v1(603,2182) v1@603,2184 ; v1(583,2079) 584,2078 v1(584,2059) v1(604,2059) 623,2059 v1(624,2058) 624,2076 v1(626,2078) 625,2079 v1(606,2079) v1(583,2079)
  Top Layer w19.29: v1(1342,2334.5) 1340,2332.5 1340,2312 ; v1@1343,2333.5 1352,2333.5 ; 1352,2342 1352,2333.5 ; v1(1354,2288) v1@1354,2287 ; 1399,2345 1399,2333.5 ; v1(1402,2288) v1@1402,2287 ; 1426,2334 1426.5,2333.5 1421.5,2333.5 1399,2333.5 ; v1(1445,2312) v1(1423,2312) ; v1@1469,2290 v1(1472,2287) ; v1(1495,2287) v1(1472,2287) ; 1340,2312 v1(1352,2312) ; 1340,2312 v1(1328,2312) 1328,2289 v1(1329,2288) 1330,2287 v1@1354,2287 ; v1(1352,2312) 1352,2324.5 1352,2333.5 ; v1(1352,2312) v1(1376,2312) ; 1352,2333.5 1399,2333.5 ; v1@1354,2287 v1@1378,2287 ; v1(1376,2312) 1376,2291 v1(1378,2289) v1@1378,2287 ; v1(1376,2312) v1(1399,2312) ; v1@1378,2287 v1@1402,2287 ; v1(1399,2312) v1(1423,2312) ; v1(1399,2312) 1399,2317.5 1399,2333.5 ; v1@1402,2287 v1(1427,2287) ; v1(1423,2312) 1423,2291 v1(1427,2287) ; v1(1427,2287) v1(1450,2287) v1(1472,2287)
  Top Layer w25: 1352,2342 1393,2383 1437,2383 ; 1399,2345 1437,2383 ; 1450,2375 1458,2383 ; U6.2@1542,2383 1458,2383 ; 1437,2383 1458,2383
  Bottom Layer w6: v1@582.83,2182.17 583,2182 v1(603,2182) 614,2182 v1(624,2182)
  Bottom Layer w17.72: v1(581,2184) 582.83,2182.17 v1@602.83,2182.17 ; v1(614,2162) v1@614,2167 ; 614,2182 v1@614,2167 ; CN1.35@648.27,2082.17 645.1,2079 v1@626,2079 ; CN1.37@648.27,2182.17 v1@624.17,2182.17 ; v1@602.83,2182.17 v1(603,2182) ; v1@602.83,2182.17 602,2183 v1(602,2204) v1(625,2204) 625,2183 v1@624.17,2182.17 ; v1@602.83,2182.17 v1@603,2182.17 ; 603,2156 599,2152 599,2086 v1@604,2081 ; 603,2156 v1(603,2182) ; 603,2156 v1@614,2167 ; v1(603,2182) v1@603,2182.17 ; v1@603,2182.17 v1@624,2182.17 ; v1@604,2058 v1(604,2059) v1@604,2078 ; v1@604,2058 585,2058 v1(584,2059) 583,2060 v1(583,2079) 584,2078 v1@604,2078 ; v1@604,2058 v1(624,2058) v1@624,2078 ; v1@604,2078 v1@606,2078 ; v1@604,2078 v1@604,2081 ; v1@604,2081 v1(606,2079) ; v1@606,2078 v1(606,2079) ; v1@606,2078 v1@624,2078 ; v1(606,2079) v1@624,2079 ; v1@624,2078 v1(626,2078) v1@626,2079 ; v1@624,2078 v1@624,2079 ; v1@624,2079 v1@626,2079 ; v1@624,2182.17 v1(624,2182) v1@624.17,2182.17 ; v1@624,2182.17 v1@624.17,2182.17
  Bottom Layer w19.29: v1(1354,2288) v1@1354,2287 ; C7.1@1387.25,2348.29 C7.1@1376,2337.04 ; v1(1402,2288) v1@1402,2287 ; 1423,2347.29 1423,2334 ; 1426,2334 1423,2334 ; C8.1@1469.93,2348.29 1469,2347.36 1469,2312 ; C9.1@1542.36,2287.42 1495.42,2287.42 v1(1495,2287) v1(1472,2287) ; v1(1328,2312) 1328,2289 v1(1329,2288) 1330,2287 v1@1354,2287 ; v1(1328,2312) v1(1352,2312) v1(1376,2312) ; v1(1328,2312) 1342,2326 v1(1342,2334.5) 1373.46,2334.5 C7.1@1376,2337.04 ; v1@1354,2287 v1@1378,2287 ; v1(1376,2312) C7.1@1376,2337.04 ; v1(1376,2312) 1376,2291 v1(1378,2289) v1@1378,2287 ; v1(1376,2312) v1(1399,2312) v1(1423,2312) ; v1@1378,2287 v1@1402,2287 ; v1@1402,2287 v1(1427,2287) ; v1(1423,2312) 1423,2334 ; v1(1423,2312) 1423,2291 v1(1427,2287) ; v1(1423,2312) v1(1445,2312) 1469,2312 ; v1(1427,2287) v1(1450,2287) v1(1472,2287) ; 1469,2312 1469,2290 v1(1472,2287)
  Bottom Layer w25: C7.1@1387.25,2348.29 1422,2348.29 ; 1423,2347.29 1422,2348.29 ; C8.1@1469.93,2348.29 1422,2348.29
pads on no net: CN1.2 CN1.3 CN1.6 CN1.7 CN1.39 CN1.41 CN1.44 CN1.45 CN1.69 CN1.73 CN1.74 CN1.119 CN1.121 CN1.160 CN1.161 CN1.162 FID1.1 FID2.1 FID3.1 FID4.1 FID5.1 FID6.1 TR1.2 TR2.2 TR3.2 TR4.2 TR5.2 TR6.2 U1.13 U1.14 U2.3 U4.13 U4.14 U5.13 U5.14 U6.7 U7.6 U8.6 U9.25 U9.26 U9.27 U10.25 U10.26 U10.27 U11.25 U11.26 U11.27 U12.25 U12.26 U12.27 U13.11 U13.12 U13.25 U13.26 U13.27 U14.11 U14.12 U14.25 U14.26 U14.27
copper on no net:
  other v1: 2807,79 2691,1018

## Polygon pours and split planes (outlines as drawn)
DGND on Top Layer "Top Layer, Top-DGND 2" (solid, pour order 22): 2930,2170 2930,155 2745,155 2745,35 3630,35 3630,330 4055,330 4055,2090 3765,2090 3440,2090 3440,2170
DGND on Top Layer "Top Layer, Top-DGND 3" (solid, remove dead copper, pour order 23): 40,2670 40,50 60,30 1920,30 1920,50 1920,210 1060,210 1060,390 980,390 980,2070 1400,2070 1400,1990 1460,1990 1560,2090 1600,2130 1660,2130 1660,2510 1660,2530 1940,2530 1940,2690 1000,2690 1000,2450 760,2450 700,2510 700,2670
DGND on Top Layer "Top Layer, Top-DGND 1" (solid, remove dead copper, pour order 21): 1360,2070 1360,290 2560,290 2560,2070 1920,2070 1920,2130 1360,2130
+5V on Top Layer "Top Layer, Top-+5V 2" (solid, pour order 18): 3490,2655 3620,2655 3620,2610 3695,2610 3695,2570 3820,2570 3820,2610 3870,2610 3870,2690 3490,2690
DGND on Top Layer "Top Layer, Top-DGND" (solid, pour order 20): 3355,2325 3355,2305 3295,2305 3295,2235 3230,2170 3070,2170 3070,2065 3105,2065 3160,2115 3440,2115 3440,2325
+5V on Top Layer "Top Layer, Top-+5V 1" (solid, pour order 19): 3175,2390 3175,2330 3455,2330 3455,2410 3455,2450 3455,2535 3475,2550 3475,2580 3420,2580 3395,2555 3395,2510 3395,2430 3175,2430 3175,2420 3175,2410
+5V on Top Layer "Top Layer, Top-+5V" (solid, pour order 17): 3425,2605 3425,2550 3485,2550 3485,2600 3505,2600 3505,2650 3455,2650 3455,2605
DGND on Bottom Layer "Bottom Layer, Bottom-DGND" (solid, remove dead copper, pour order 32): 30,2690 30,40 50,20 4030,20 4060,50 4060,2670 4040,2690
+1V8 on Bottom Layer "Bottom Layer, Bottom-+1V8 1" (solid, pour order 31): 940,640 940,605 940,285 1020,205 1395,205 1400,210 1400,290 1340,290 1330,280 1320,270 1065,270 1065,505 1010,560 1010,640
+1V8 on Bottom Layer "Bottom Layer, Bottom-+1V8" (solid, pour order 30): 2460,675 2460,615 2575,615 2575,650 2660,650 2690,680 2690,785 2780,785 2805,810 2925,810 2970,855 2970,915 2940,915 2940,900 2890,850 2885,845 2775,845 2770,840 2630,840 2630,825 2630,820 2565,820 2565,685 2555,675
+5V on MidLayer1 "Mid-Layer 1, IN1-+5V" (solid, remove dead copper, pour order 29): 1536,2061 1536,1946 1536,1366 1536,636 1536,306 2496,306 2496,56 4046,56 4046,2416 4046,2626 4046,2656 3186,2656 3170,2655 3170,2295 3120,2295 3120,2005 3026,2006 3026,2226 2746,2226 2601,2081 1536,2081
DGND on MidLayer1 "Mid-Layer 1, IN1-DGND 2" (solid, remove dead copper, pour order 28): 40,30 1510,30 1510,2050 1400,2050 1400,2160 980,2160 980,2130 40,2130
DGND on MidLayer1 "Mid-Layer 1, IN1-DGND 1" (solid, remove dead copper, pour order 27): 30,2125 480,2125 480,2385 460,2385 460,2455 1530,2455 1530,2700 55,2700 30,2675
VDD_12V on MidLayer1 "Mid-Layer 1, IN1-VDD_12V" (solid, pour order 26): 650,2160 960,2160 960,2190 1150,2190 1510,2190 1510,2440 960,2440 490,2440 490,2050 510,2030 650,2030
+1V8_A on MidLayer1 "Mid-Layer 1, IN1-+1V8_A" (solid, pour order 24): 1430,2150 1430,2070 1490,2070 1520,2100 2590,2100 2730,2240 2845,2240 3010,2240 3015,2240 3030,2240 3030,2170 3030,2020 3070,2020 3070,2295 3060,2295 2385,2295 2310,2220 1710,2220 1670,2180 1640,2150
DGND on MidLayer1 "Mid-Layer 1, IN1-DGND" (solid, pour order 25): 1525,2700 1525,2170 1630,2170 1700,2240 2005,2240 2005,2580 2005,2660 2005,2700
DGND on InternalPlane1 (split plane): 4047.62,2694.71 4051.72,2691.05 4054.9,2687.49 4054.9,26.85 4051.72,23.28 4048.15,20.1 27.59,20.1 24.03,23.28 20.37,27.38 20.1,27.76 20.1,2686.57 20.37,2686.95 24.03,2691.05 28.13,2694.71 28.4,2694.9 4047.35,2694.9
+1V8 on Internal Plane 3 (split plane): 3603.95,2305 3603.95,2166.05 2985,2166.05 2983.43,2165.85 2981.97,2165.24 2980.72,2164.28 2979.76,2163.03 2979.15,2161.57 2978.95,2160 2978.95,826.05 2846.05,826.05 2846.05,1168.95 2855,1168.95 2856.57,1169.15 2858.03,1169.76 2859.28,1170.72 2860.24,1171.97 2860.85,1173.43 2861.05,1175 2861.05,1235 2861.05,1375 2860.85,1376.57 2860.24,1378.03 2859.28,1379.28 2858.03,1380.24 2856.57,1380.85 2855,1381.05 2841.05,1381.05 2841.05,1665 2840.85,1666.57 2840.24,1668.03 2839.28,1669.28 2838.03,1670.24 2836.57,1670.85 2835,1671.05 2806.05,1671.05 2806.05,1975 2806.05,1991 2805.85,1992.57 2805.24,1994.03 2804.28,1995.28 2803.03,1996.24 2801.57,1996.85 2800,1997.05 2655,1997.05 2653.43,1996.85 2651.97,1996.24 2650.72,1995.28 2649.76,1994.03 2649.15,1992.57 2648.95,1991 2648.95,1946.05 2501.05,1946.05 2501.05,1965 2501.05,2029.73 2501.53,2034.95 2594,2034.95 2595.57,2035.15 2597.03,2035.76 2598.28,2036.72 2619.28,2057.72 2620.24,2058.97 2620.85,2060.43 2621.05,2062 2621.05,2170 2621.05,2258.95 3475,2258.95 3476.57,2259.15 3478.03,2259.76 3479.28,2260.72 3480.24,2261.97 3480.85,2263.43 3481.05,2265 3481.05,2308.95 3603.95,2308.95
+1V8_A on Internal Plane 3 (split plane): 1488.95,1750 1489.15,1748.43 1489.76,1746.97 1490.72,1745.72 1491.97,1744.76 1493.43,1744.15 1495,1743.95 1532.49,1743.95 1558.95,1717.49 1558.95,1531.05 1480,1531.05 1478.43,1530.85 1476.97,1530.24 1475.72,1529.28 1474.76,1528.03 1474.15,1526.57 1473.95,1525 1473.95,1245 1473.95,1070 1474.15,1068.43 1474.76,1066.97 1475.72,1065.72 1476.97,1064.76 1478.43,1064.15 1480,1063.95 1567.49,1063.95 1583.95,1047.49 1583.95,747.51 1557.49,721.05 1432.51,721.05 1406.05,747.51 1406.05,1295 1406.03,1295.19 1406.04,1295.39 1405.92,1295.98 1405.85,1296.57 1405.77,1296.75 1405.73,1296.94 1405.47,1297.47 1405.24,1298.03 1405.12,1298.18 1405.04,1298.36 1396.05,1311.83 1396.05,1587.49 1404.28,1595.72 1405.24,1596.97 1405.85,1598.43 1406.05,1600 1406.05,1670 1405.85,1671.57 1405.24,1673.03 1404.28,1674.28 1403.03,1675.24 1401.57,1675.85 1400,1676.05 1396.05,1676.05 1396.05,2158.95 1488.95,2158.95
+1V8_A on Internal Plane 3 (split plane): 3923.95,2190 3923.95,2155 3923.95,2141.05 3766.05,2141.05 3766.05,2190 3765.85,2191.57 3765.24,2193.03 3764.28,2194.28 3763.03,2195.24 3761.57,2195.85 3760,2196.05 3675,2196.05 3673.43,2195.85 3671.97,2195.24 3670.72,2194.28 3669.76,2193.03 3669.15,2191.57 3668.95,2190 3668.95,2041.05 3115,2041.05 3113.43,2040.85 3111.97,2040.24 3110.72,2039.28 3109.76,2038.03 3109.15,2036.57 3108.95,2035 3108.95,2020 3108.95,1330 3108.95,651.05 2900,651.05 2898.43,650.85 2896.97,650.24 2895.72,649.28 2815.72,569.28 2745.72,499.28 2744.76,498.03 2744.15,496.57 2743.95,495 2743.95,235 2743.95,231.05 2671.05,231.05 2671.05,900 2671.05,1603.95 2738.95,1603.95 2738.95,750 2739.15,748.43 2739.76,746.97 2740.72,745.72 2741.97,744.76 2743.43,744.15 2745,743.95 2985,743.95 2986.57,744.15 2988.03,744.76 2989.28,745.72 2990.24,746.97 2990.85,748.43 2991.05,750 2991.05,2153.95 3610,2153.95 3611.57,2154.15 3613.03,2154.76 3614.28,2155.72 3615.24,2156.97 3615.85,2158.43 3616.05,2160 3616.05,2298.95 3923.95,2298.95
+1V8 on Internal Plane 3 (split plane): 159 vertices, not listed, extent 1236.05,131.05 2508.95,1663.95
+1V8_A on Internal Plane 3 (split plane): 1078.95,1510 1079.15,1508.43 1079.76,1506.97 1080.72,1505.72 1081.97,1504.76 1083.43,1504.15 1085,1503.95 1158.95,1503.95 1158.95,1140 1158.95,941.05 1090,941.05 1088.43,940.85 1086.97,940.24 1085.72,939.28 1084.76,938.03 1084.15,936.57 1083.95,935 1083.95,875 1084.15,873.43 1084.76,871.97 1085.72,870.72 1153.95,802.49 1153.95,680 1153.95,455 1153.95,246.05 1031.05,246.05 1031.05,313.95 1060,313.95 1061.57,314.15 1063.03,314.76 1064.28,315.72 1065.24,316.97 1065.85,318.43 1066.05,320 1066.05,570 1066.05,810 1065.85,811.57 1065.24,813.03 1064.28,814.28 1021.05,857.51 1021.05,952.49 1024.28,955.72 1074.28,1005.72 1074.82,1006.43 1075.24,1006.97 1075.42,1007.4 1075.85,1008.43 1076.05,1010 1076.05,1385 1075.85,1386.57 1075.24,1388.03 1074.28,1389.28 1073.03,1390.24 1071.57,1390.85 1070,1391.05 1016.05,1391.05 1016.05,1668.95 1078.95,1668.95
+1V8 on Internal Plane 3 (split plane): 1003.95,1851.05 915,1851.05 913.43,1850.85 911.97,1850.24 910.72,1849.28 909.76,1848.03 909.15,1846.57 908.95,1845 908.95,1775 909.15,1773.43 909.76,1771.97 910.72,1770.72 911.97,1769.76 913.43,1769.15 915,1768.95 1003.95,1768.95 1003.95,1675 1003.95,1385 1003.95,1380 1004.15,1378.43 1004.76,1376.97 1005.72,1375.72 1006.97,1374.76 1008.43,1374.15 1010,1373.95 1063.95,1373.95 1063.95,1012.51 1015.72,964.28 1010.72,959.28 1009.76,958.03 1009.15,956.57 1008.95,955 1008.95,855 1009.15,853.43 1009.76,851.97 1010.72,850.72 1053.95,807.49 1053.95,606.05 906.05,606.05 906.05,890 906.05,1013.95 970,1013.95 971.57,1014.15 973.03,1014.76 974.28,1015.72 975.24,1016.97 975.85,1018.43 976.05,1020 976.05,1120 975.85,1121.57 975.24,1123.03 974.28,1124.28 973.03,1125.24 971.57,1125.85 970,1126.05 921.05,1126.05 921.05,1265 920.85,1266.57 920.24,1268.03 919.28,1269.28 918.03,1270.24 916.57,1270.85 915,1271.05 839.05,1271.05 839.05,2093.95 1003.95,2093.95
+3V3 on Internal Plane 3 (split plane): 4047.62,2694.71 4051.72,2691.05 4054.9,2687.49 4054.9,26.85 4051.72,23.28 4048.15,20.1 27.59,20.1 24.03,23.28 20.37,27.38 20.1,27.76 20.1,2686.57 20.37,2686.95 24.03,2691.05 28.13,2694.71 28.4,2694.9 4047.35,2694.9
DGND on InternalPlane2 (split plane): 4047.62,2694.71 4051.72,2691.05 4054.9,2687.49 4054.9,26.85 4051.72,23.28 4048.15,20.1 27.59,20.1 24.03,23.28 20.37,27.38 20.1,27.76 20.1,2686.57 20.37,2686.95 24.03,2691.05 28.13,2694.71 28.4,2694.9 4047.35,2694.9

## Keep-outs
Keep-Out Layer:
  text ".Layer_Name" at 577,-858.49 h60

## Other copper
Top Layer:
  pour cut-out: 2235,1020 2235,705 2575,705 2575,1020
  pour cut-out: 2240,1695 2240,1380 2580,1380 2580,1695
  pour cut-out: 2240,325 2240,10 2580,10 2580,325
  pour cut-out: 3630,1010 3630,695 3970,695 3970,1010
  pour cut-out: 3630,1010 3630,695 3970,695 3970,1010
  pour cut-out: 3625,1700 3625,1385 3965,1385 3965,1700
  text ".Layer_Name" at 577,-858.49 h60
MidLayer1:
  text ".Layer_Name" at 575,-861.49 h60
Bottom Layer:
  text ".Layer_Name" at 577,-858.49 h60
InternalPlane1 (plane layer: these items are gaps in the copper):
  lines w20: 4010,-1.1 58.7,-1.1 cw(c58.7,57.95) -0.35,57.95 -0.35,2656.38 cw(c58.7,2656.38) 58.7,2715.43 4015,2715.4 ; 4017.05,-1.1 ccw(c4017.05,57.95) 4076.1,57.95 ; 4017.05,2715.43 cw(c4017.05,2656.38) 4076.1,2656.38 ; 4076.1,47.95 4076.1,2646.38
  text ".Layer_Name" at 572,-856.49 h60
InternalPlane2 (plane layer: these items are gaps in the copper):
  lines w20: 4010,-1.1 58.7,-1.1 cw(c58.7,57.95) -0.35,57.95 -0.35,2656.38 cw(c58.7,2656.38) 58.7,2715.43 4015,2715.4 ; 4017.05,-1.1 ccw(c4017.05,57.95) 4076.1,57.95 ; 4017.05,2715.43 cw(c4017.05,2656.38) 4076.1,2656.38 ; 4076.1,47.95 4076.1,2646.38
  text ".Layer_Name" at 569,-856.49 h60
